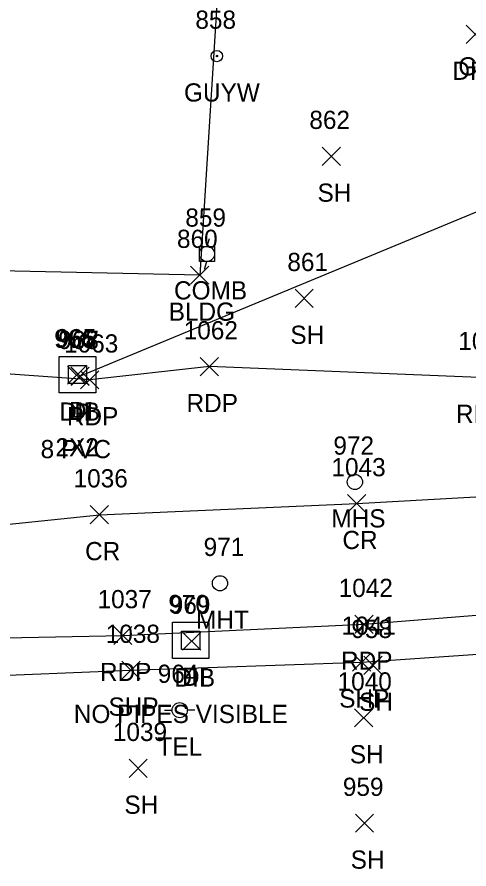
# Model space of a CAD drawing. Extents: x 1716490 to 1717645, y 888034 to 890004.
# Drawn here: x 1716763.9 to 1716813.5, y 888186.1 to 888279.7 of the extents above; entities that cross this region are included whole.
import ezdxf

# ---------------------------------------------------------------- set-up
doc = ezdxf.new("R2010")
doc.units = 0
for name, color, linetype in [('D_A', 7, 'Continuous'), ('D_C', 7, 'Continuous'), ('D_I', 7, 'Continuous'), ('D_TIC', 7, 'Continuous'), ('DCP', 7, 'Continuous'), ('DS', 7, 'Continuous'), ('L_A', 7, 'Continuous'), ('L_I', 7, 'Continuous'), ('L_TIC', 7, 'Continuous'), ('LBC', 7, 'Continuous'), ('P_A', 7, 'Continuous'), ('P_I', 7, 'Continuous'), ('P_TIC', 7, 'Continuous'), ('PET', 7, 'Continuous'), ('PRC', 7, 'Continuous'), ('PSP', 7, 'Continuous'), ('R_A', 7, 'Continuous'), ('R_TIC', 7, 'Continuous'), ('U_A', 7, 'Continuous'), ('U_I', 7, 'Continuous'), ('UP', 7, 'Continuous'), ('UPGW', 7, 'Continuous'), ('USMH', 7, 'Continuous'), ('UTMH', 7, 'Continuous')]:
    doc.layers.add(name, color=color, linetype=linetype)

msp = doc.modelspace()

# ---------------------------------------------------------------- linework, layer by layer
at = {"layer": 'D_TIC'}
for points in [[(1716769.486, 888239.392), (1716771.486, 888241.392)], [(1716771.486, 888239.392), (1716769.486, 888241.392)], [(1716769.869, 888239.276), (1716771.869, 888241.276)], [(1716771.869, 888239.276), (1716769.869, 888241.276)], [(1716769.874, 888239.265), (1716771.874, 888241.265)], [(1716771.874, 888239.265), (1716769.874, 888241.265)], [(1716782.125, 888210.163), (1716784.125, 888212.163)], [(1716784.125, 888210.163), (1716782.125, 888212.163)]]:
    msp.add_lwpolyline(points, dxfattribs=at)
at = {"layer": 'DCP'}
msp.add_lwpolyline([(1716831.837, 888265.562), (1716770.869, 888240.276)], dxfattribs=at)
at = {"layer": 'DS'}
for p, q in [((1716768.579, 888242.455), (1716772.579, 888242.455)), ((1716768.579, 888238.455), (1716768.579, 888242.455)), ((1716772.579, 888242.455), (1716772.579, 888238.455)), ((1716769.579, 888239.455), (1716769.579, 888241.455)), ((1716769.579, 888241.455), (1716771.579, 888241.455)), ((1716771.579, 888241.455), (1716771.579, 888239.455)), ((1716770.584, 888240.456), (1716770.584, 888240.456)), ((1716770.584, 888240.456), (1716770.584, 888240.456)), ((1716771.579, 888239.455), (1716769.579, 888239.455)), ((1716772.579, 888238.455), (1716768.579, 888238.455)), ((1716780.996, 888213.242), (1716784.996, 888213.242)), ((1716780.996, 888209.242), (1716780.996, 888213.242)), ((1716784.996, 888213.242), (1716784.996, 888209.242)), ((1716781.996, 888210.242), (1716781.996, 888212.242)), ((1716781.996, 888212.242), (1716783.996, 888212.242)), ((1716783.996, 888212.242), (1716783.996, 888210.242)), ((1716783.001, 888211.243), (1716783.001, 888211.243)), ((1716783.001, 888211.243), (1716783.001, 888211.243)), ((1716783.996, 888210.242), (1716781.996, 888210.242)), ((1716784.996, 888209.242), (1716780.996, 888209.242))]:
    msp.add_line(p, q, dxfattribs=at)
at = {"layer": 'L_TIC'}
for points in [[(1716797.441, 888263.444), (1716799.441, 888265.444)], [(1716799.441, 888263.444), (1716797.441, 888265.444)], [(1716783.001, 888250.37), (1716785.001, 888252.37)], [(1716785.001, 888250.37), (1716783.001, 888252.37)], [(1716794.46, 888247.826), (1716796.46, 888249.826)], [(1716796.46, 888247.826), (1716794.46, 888249.826)], [(1716802.006, 888207.503), (1716804.006, 888209.503)], [(1716804.006, 888207.503), (1716802.006, 888209.503)], [(1716800.989, 888201.734), (1716802.989, 888203.734)], [(1716802.989, 888201.734), (1716800.989, 888203.734)], [(1716776.243, 888196.187), (1716778.243, 888198.187)], [(1716778.243, 888196.187), (1716776.243, 888198.187)], [(1716801.079, 888190.155), (1716803.079, 888192.155)], [(1716803.079, 888190.155), (1716801.079, 888192.155)]]:
    msp.add_lwpolyline(points, dxfattribs=at)
at = {"layer": 'LBC'}
msp.add_lwpolyline([(1716790.149, 888346.756), (1716790.149, 888340.324), (1716789.905, 888340.162), (1716789.239, 888334.166), (1716788.401, 888319.776), (1716786.544, 888291.649), (1716784.001, 888251.37), (1716721.337, 888252.742), (1716722.055, 888265.932)], dxfattribs=at)
at = {"layer": 'P_TIC'}
for points in [[(1716784.061, 888240.323), (1716786.061, 888242.323)], [(1716786.061, 888240.323), (1716784.061, 888242.323)], [(1716770.928, 888238.872), (1716772.928, 888240.872)], [(1716772.928, 888238.872), (1716770.928, 888240.872)], [(1716800.229, 888225.279), (1716802.229, 888227.279)], [(1716802.229, 888225.279), (1716800.229, 888227.279)], [(1716771.982, 888224.054), (1716773.982, 888226.054)], [(1716773.982, 888224.054), (1716771.982, 888226.054)], [(1716801.021, 888212.013), (1716803.021, 888214.013)], [(1716803.021, 888212.013), (1716801.021, 888214.013)], [(1716774.556, 888210.777), (1716776.556, 888212.777)], [(1716776.556, 888210.777), (1716774.556, 888212.777)], [(1716800.777, 888207.857), (1716802.777, 888209.857)], [(1716802.777, 888207.857), (1716800.777, 888209.857)], [(1716775.451, 888206.971), (1716777.451, 888208.971)], [(1716777.451, 888206.971), (1716775.451, 888208.971)]]:
    msp.add_lwpolyline(points, dxfattribs=at)
at = {"layer": 'PET'}
msp.add_lwpolyline([(1716669.133, 888208.315), (1716709.505, 888208.714), (1716740.373, 888211.068), (1716775.556, 888211.777), (1716802.021, 888213.013), (1716840.455, 888216.113), (1716878.657, 888218.974), (1716877.597, 888230.504), (1716876.883, 888242.851), (1716857.915, 888241.594), (1716836.634, 888239.831), (1716814.633, 888240.145), (1716785.061, 888241.323), (1716771.928, 888239.872), (1716746.815, 888241.658), (1716719.438, 888242.78), (1716699.752, 888242.907), (1716680.829, 888242.531), (1716671.322, 888244.592)], dxfattribs=at)
at = {"layer": 'PRC'}
msp.add_lwpolyline([(1716669.076, 888220.596), (1716706.499, 888221.389), (1716739.728, 888221.602), (1716772.982, 888225.054), (1716801.229, 888226.279), (1716838.45, 888228.358), (1716877.597, 888230.504)], dxfattribs=at)
at = {"layer": 'PSP'}
msp.add_lwpolyline([(1716669.372, 888204.532), (1716709.372, 888205.407), (1716740.477, 888206.521), (1716776.451, 888207.971), (1716801.777, 888208.857), (1716839.964, 888211.481)], dxfattribs=at)
at = {"layer": 'R_TIC'}
for points in [[(1716813.245, 888276.838), (1716815.245, 888278.838)], [(1716815.245, 888276.838), (1716813.245, 888278.838)]]:
    msp.add_lwpolyline(points, dxfattribs=at)
at = {"layer": 'UP'}
for p, q in [((1716785.04, 888255.374), (1716784.79, 888254.541)), ((1716783.957, 888252.874), (1716783.957, 888254.541)), ((1716783.957, 888254.541), (1716785.624, 888254.541)), ((1716785.624, 888254.541), (1716785.624, 888252.874)), ((1716784.79, 888253.708), (1716784.79, 888253.708)), ((1716785.624, 888252.874), (1716783.957, 888252.874)), ((1716784.54, 888252.041), (1716784.79, 888252.874)), ((1716780.142, 888203.571), (1716780.968, 888203.571)), ((1716781.801, 888203.577), (1716781.801, 888203.577)), ((1716783.468, 888203.577), (1716782.635, 888203.577)), ((1716782.635, 888203.577), (1716782.635, 888203.577)), ((1716783.468, 888203.577), (1716783.468, 888203.577))]:
    msp.add_line(p, q, dxfattribs=at)
for centre in [(1716784.79, 888253.708), (1716781.801, 888203.577)]:
    msp.add_circle(centre, 0.833, dxfattribs=at)
at = {"layer": 'UPGW'}
for radius in [0.625, 0.0833]:
    msp.add_circle((1716785.881, 888275.453), radius, dxfattribs=at)
at = {"layer": 'USMH'}
for p, q in [((1716801.031, 888228.653), (1716801.031, 888228.653)), ((1716801.864, 888228.653), (1716801.864, 888228.653))]:
    msp.add_line(p, q, dxfattribs=at)
msp.add_circle((1716801.031, 888228.653), 0.833, dxfattribs=at)
at = {"layer": 'UTMH'}
for p, q in [((1716786.222, 888217.519), (1716786.222, 888217.519)), ((1716787.056, 888217.519), (1716787.056, 888217.519))]:
    msp.add_line(p, q, dxfattribs=at)
msp.add_circle((1716786.222, 888217.519), 0.833, dxfattribs=at)

# ---------------------------------------------------------------- texts
at = {"layer": 'D_A'}
for s, p in [('DIB', (1716768.588, 888235.392)), ('DI', (1716769.639, 888235.456)), ('P', (1716770.247, 888235.276)), ('P', (1716770.252, 888235.265)), ('DIB', (1716781.227, 888206.163)), ('DI', (1716782.056, 888206.243))]:
    msp.add_text(s, height=2, dxfattribs=at).set_placement(p)
at = {"layer": 'D_C'}
for s, p in [('8 PVC', (1716766.535, 888231.265)), ('2X2', (1716768.159, 888231.456)), ('NO PIPES VISIBLE', (1716770.18, 888202.163))]:
    msp.add_text(s, height=2, dxfattribs=at).set_placement(p)
at = {"layer": 'D_I'}
for s, p in [('966', (1716768.021, 888243.392)), ('965', (1716768.175, 888243.456)), ('967', (1716768.459, 888243.276)), ('968', (1716768.465, 888243.265)), ('970', (1716780.552, 888214.243)), ('969', (1716780.708, 888214.163))]:
    msp.add_text(s, height=2, dxfattribs=at).set_placement(p)
at = {"layer": 'L_A'}
for s, p in [('SH', (1716796.929, 888259.444)), ('BLDG', (1716780.592, 888246.37)), ('SH', (1716793.948, 888243.826)), ('SH', (1716801.494, 888203.503)), ('SH', (1716800.477, 888197.734)), ('SH', (1716775.732, 888192.187)), ('SH', (1716800.567, 888186.155))]:
    msp.add_text(s, height=2, dxfattribs=at).set_placement(p)
at = {"layer": 'L_I'}
for s, p in [('862', (1716796.032, 888267.444)), ('860', (1716781.505, 888254.37)), ('861', (1716793.617, 888251.826)), ('958', (1716800.644, 888211.503)), ('1040', (1716799.131, 888205.734)), ('1039', (1716774.464, 888200.187)), ('959', (1716799.709, 888194.155))]:
    msp.add_text(s, height=2, dxfattribs=at).set_placement(p)
at = {"layer": 'P_A'}
for s, p in [('RDP', (1716782.549, 888236.323)), ('RDP', (1716769.416, 888234.872)), ('RDP', (1716812.121, 888235.145)), ('CR', (1716799.662, 888221.279)), ('CR', (1716771.415, 888220.054)), ('RDP', (1716799.509, 888208.013)), ('RDP', (1716773.045, 888206.777)), ('SHP', (1716799.313, 888203.857)), ('SHP', (1716773.987, 888202.971))]:
    msp.add_text(s, height=2, dxfattribs=at).set_placement(p)
at = {"layer": 'P_I'}
for s, p in [('1062', (1716782.242, 888244.323)), ('1061', (1716812.381, 888243.145)), ('1063', (1716769.109, 888242.872)), ('1043', (1716798.457, 888229.279)), ('1036', (1716770.155, 888228.054)), ('1042', (1716799.249, 888216.013)), ('1037', (1716772.785, 888214.777)), ('1041', (1716799.572, 888211.857)), ('1038', (1716773.68, 888210.971))]:
    msp.add_text(s, height=2, dxfattribs=at).set_placement(p)
at = {"layer": 'R_A'}
for s, p in [('GRL', (1716812.382, 888273.323)), ('DRP', (1716811.733, 888272.838))]:
    msp.add_text(s, height=2, dxfattribs=at).set_placement(p)
at = {"layer": 'U_A'}
for s, p in [('GUYW', (1716782.275, 888270.453)), ('COMB', (1716781.176, 888248.708)), ('MHS', (1716798.448, 888223.653)), ('MHT', (1716783.6, 888212.519)), ('TEL', (1716779.361, 888198.577))]:
    msp.add_text(s, height=2, dxfattribs=at).set_placement(p)
at = {"layer": 'U_I'}
for s, p in [('858', (1716783.519, 888278.453)), ('859', (1716782.42, 888256.708)), ('972', (1716798.669, 888231.653)), ('971', (1716784.427, 888220.519)), ('964', (1716779.392, 888206.577))]:
    msp.add_text(s, height=2, dxfattribs=at).set_placement(p)

doc.saveas('drawing.dxf')
